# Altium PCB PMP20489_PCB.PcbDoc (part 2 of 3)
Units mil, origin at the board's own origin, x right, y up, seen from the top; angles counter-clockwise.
Board outline 4000 x 6000 mil, 8 copper layers (Top Layer, Signal Layer 1, Signal Layer 2, Signal Layer 3, Signal Layer 4, Signal Layer 5, Signal Layer 6, Bottom Layer), stack 63 mil thick; 331 components, 128 nets, 876 pads, 1027 vias.
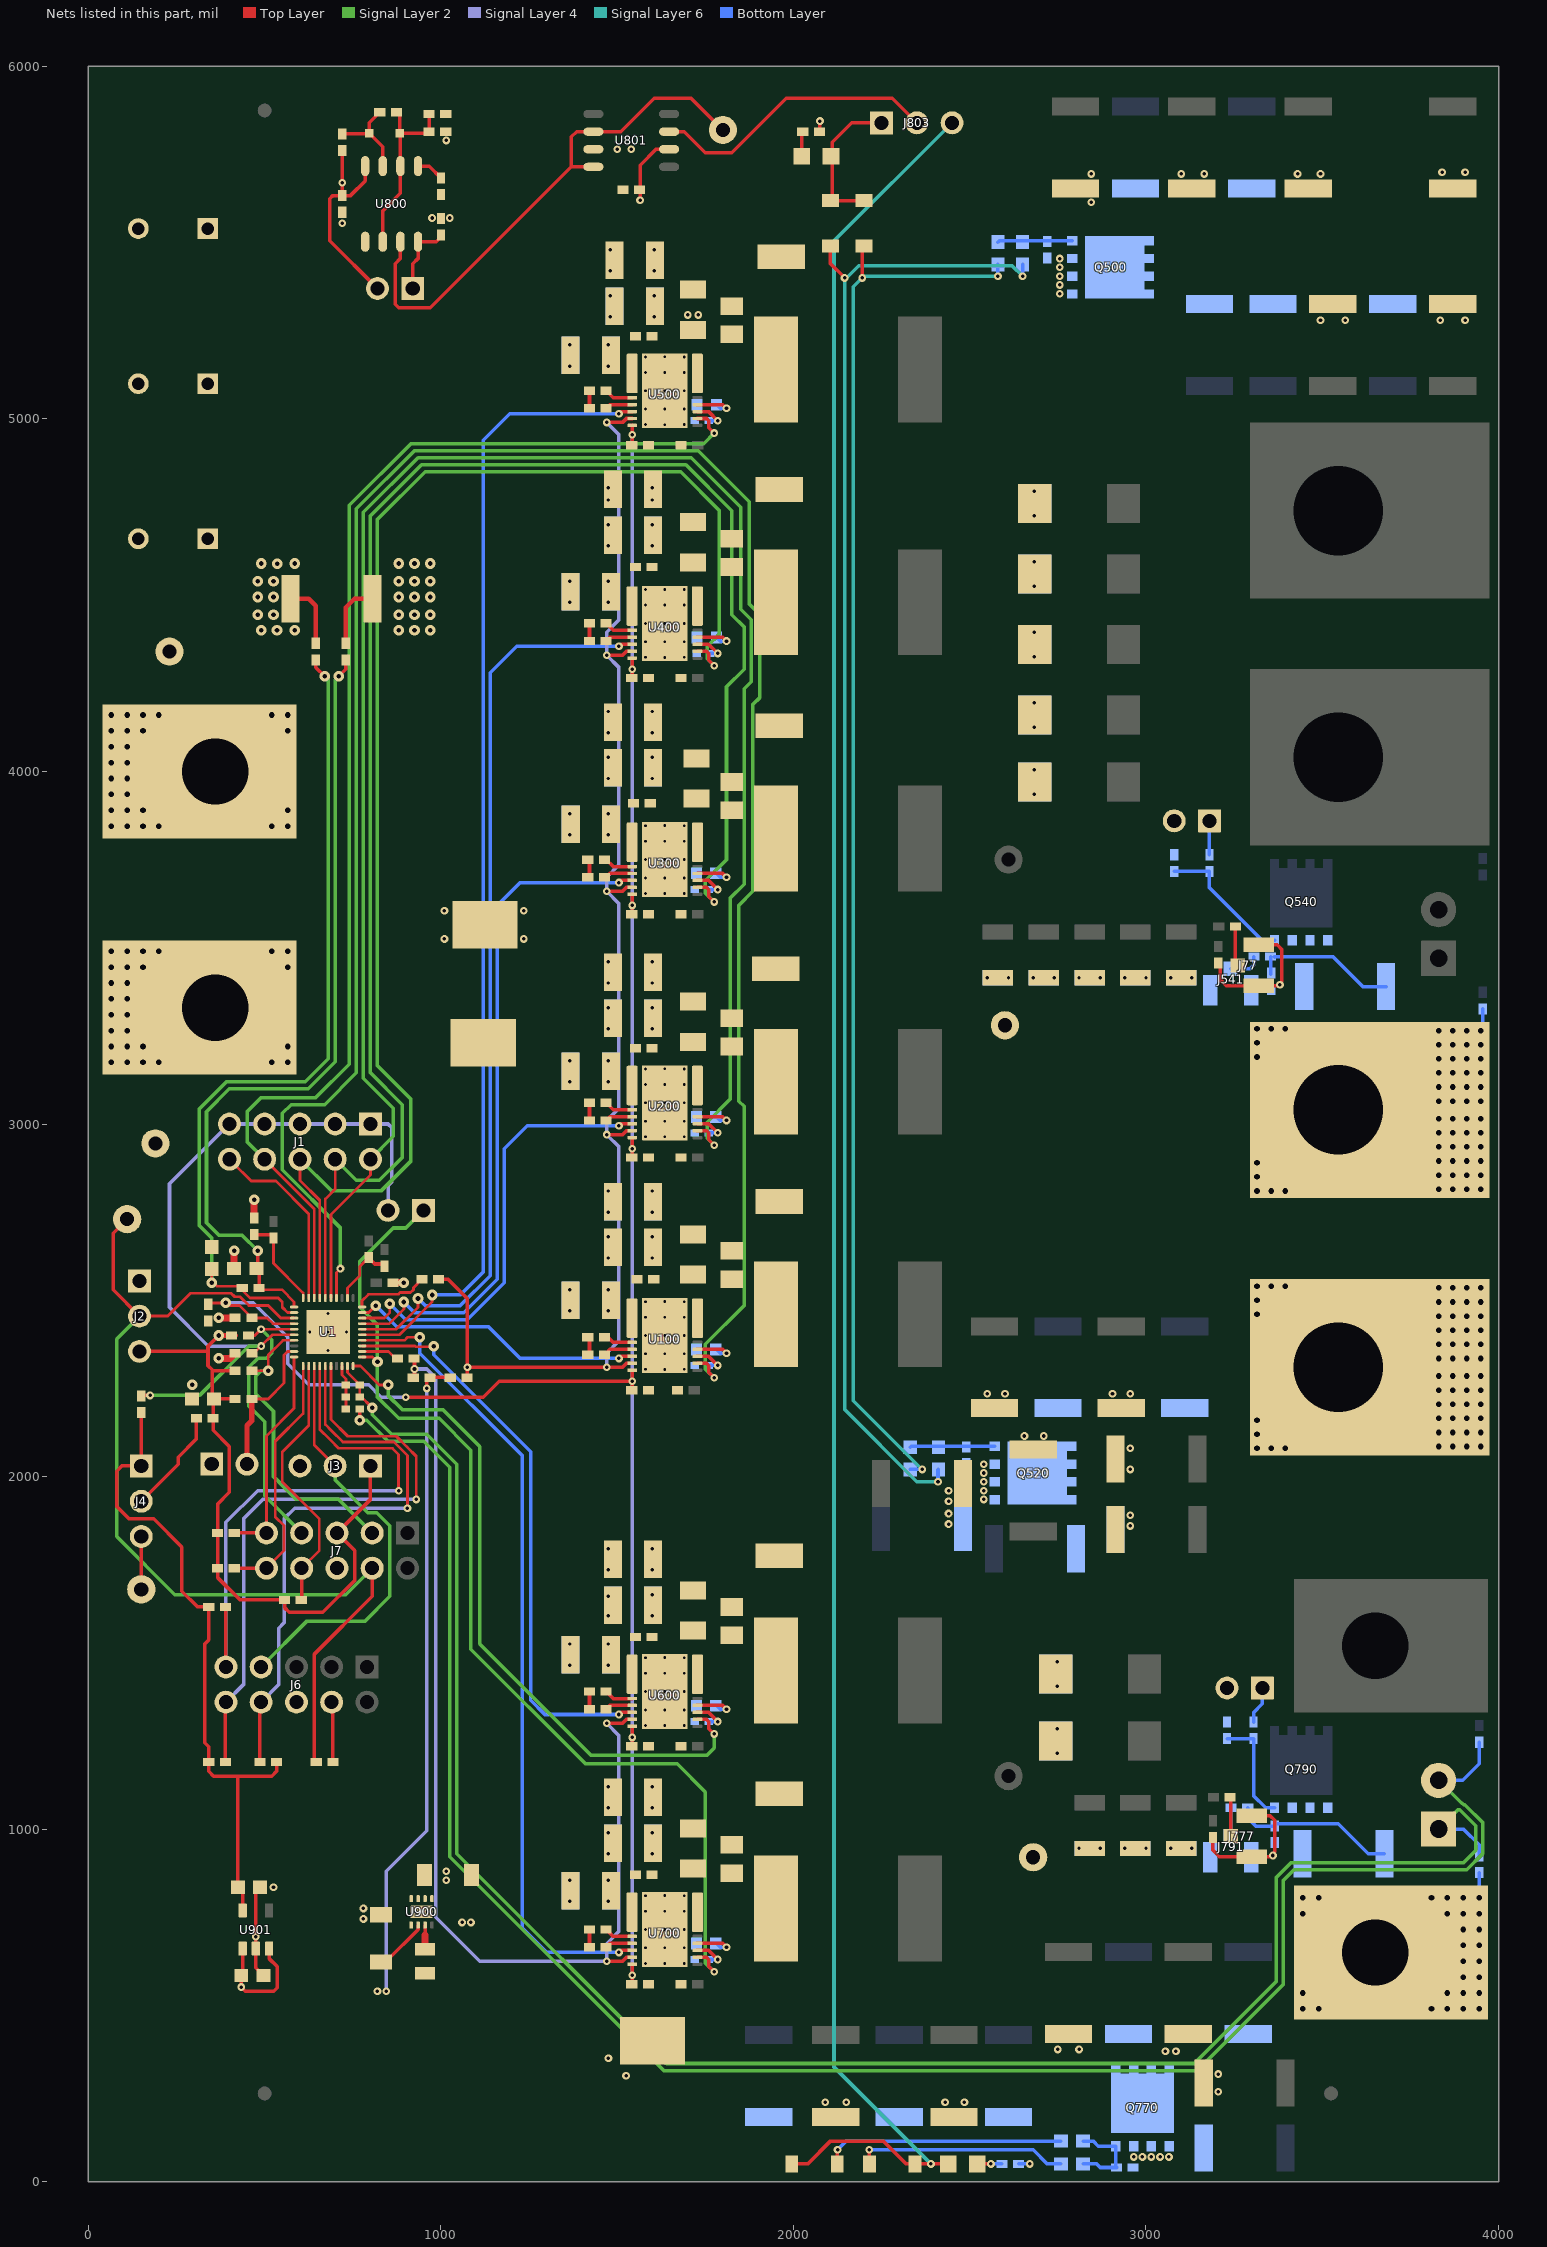
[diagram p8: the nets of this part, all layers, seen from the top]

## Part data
C1: "CAP, CERM, 4.7 µF, 10 V, +/- 20%, X5R, 0402"
C2 C7 C8 C902 C903: "CAP, CERM, 1 µF, 25 V, +/- 10%, X5R, 0603"
C3 C6: "CAP, CERM, 1 µF, 10 V, +/- 10%, X7S, 0402"
C4: "CAP, CERM, 2200 pF, 50 V, +/- 10%, X7R, 0402"
C5 C60: "CAP, CERM, 1000 pF, 50 V, +/- 10%, X7R, 0402"
C11 C12 C13: "CAP, AL, 470 µF, 35 V, +/- 20%, TH"
C21 C22 C23 C24 C25 C26 C27 C28 C29 C30 C721 C722 C723 C724: "CAP, Aluminum Polymer, 470 µF, 2.5 V, +/- 20%, 9 ohm, 7.3x1.8x4.3mm SMD"
C31 C32 C33 C34 C35 C36 C37 C38 C39 C40 C725 C726 C727 C728 C729 C730: "CAP, CERM, 100 µF, 6.3 V, +/- 20%, X5R, 1210"
C77 C110 C210 C310 C410 C510 C540 C610 C710 C777 C790: "CAP, CERM, 0.1 µF, 25 V, +/- 10%, X5R, 0402"
C100 C200 C300 C400 C500 C600 C700: "CAP, CERM, 1000 pF, 25 V, +/- 5%, C0G/NP0, 0402"
C101 C102 C103 C104 C105 C201 C202 C203 C204 C205 C301 C302 C303 C304 C305 C401 C402 C403 C404 C405 C501 C502 C503 C504 C505 C601 C602 C603 C604 C605 C701 C702 C703 C704 C705: "CAP, CERM, 22 µF, 16 V, +/- 20%, X5R, 1210"
C106 C206 C306 C406 C506 C606 C706: "CAP, CERM, 3300 pF, 50 V, +/- 10%, X7R, 0402"
C111 C211 C311 C411 C511 C611 C711: "CAP, CERM, 10 µF, 6.3 V, +/- 20%, X5R, 0603"
C112 C212 C312 C412 C512 C612 C712: "CAP, CERM, 0.1 µF, 16 V, +/- 10%, X5R, 0402"
C113 C213 C313 C413 C513 C613 C713: "CAP, CERM, 1500 pF, 100 V, +/- 10%, X7R, 0805"
C800 C801 C802 C803: "CAP, CERM, 0.1 µF, 50 V, +/- 20%, X7R, 0402"
C804: "CAP, CERM, 1 µF, 10 V, +/- 10%, X5R, 0402"
C900: "CAP, CERM, 10 µF, 25 V, +/- 10%, X5R, 1206"
C901: "CAP, CERM, 22 µF, 6.3 V, +/- 10%, X5R, 1206"
D500: "LED, Red, SMD"
D502 D503 D770 D771: "Diode, Schottky, 30 V, 0.5 A, SOD-123"
D772: "LED, Green, SMD"
D800: "Diode, Schottky, 30 V, 0.2 A, SOD-323"
Dyn_Clk TP1 TP2 VIN Vout VoutB: "Test Point, Miniature, Red, TH"
FID1 FID2 FID3 FID4 FID5 FID6: "Fiducial mark.  There is nothing to buy or mount."
H1 H2 H3 H4: "Bumpon, Hemisphere, 0.375 X 0.235, Black"
J1 J7: "Header, 100mil, 5x2, Tin, TH"
J2 J3 J4 J803: "Header, 100mil, 3x1, Gold, TH"
J5 J8 J540 J790 J800: "Header, 100mil, 2x1, Gold, TH"
J6: "Header (shrouded), 100mil, 5x2, Gold, TH"
J11 J12 J701 J702: "Terminal 50A Lug"
J14 J703: "Terminal Block, 3.5mm Pitch, 2x1, TH"
J15 J16 J17 J18: "Terminal 90A Lug"
J77 J541 J777 J791: "Connector, Ultra-Mini Coaxial, SMD"
L100 L200 L300 L400 L500 L600 L700: "Inductor, Shielded Drum Core, Metal Composite, 210 nH, 68 A, 0.2 ohm, SMD"
L900: "Inductor, Shielded, Ferrite, 2.2 µH, 1.26 A, 0.066 ohm, SMD"
LBL1: library part THT-14-423-10, "Thermal Transfer Printable Labels, 0.650\" W x 0.200\" H - 10,000 per roll"
Logo3: library part FCC_disclaimer, "FCC_disclaimer"
Q500 Q520 Q770: "MOSFET, N-CH, 25 V, 113 A, DualCool SON 5x6mm"
Q540 Q790: "MOSFET, N-CH, 25 V, 100 A, SON 5x6mm"
R1 R10 R16: "RES, 1.0, 5%, 0.063 W, 0402"
R2 R6 R9: "RES, 9.76 M, 1%, 0.063 W, 0402"
R3: "RES, 121 k, 1%, 0.063 W, 0402"
R4: "RES, 412 k, 1%, 0.063 W, 0402"
R5: "RES, 154 k, 1%, 0.063 W, 0402"
R7 R8 R14 R23 R24 R25: "RES, 4.75 k, 1%, 0.063 W, 0402"
R11 R62 R66 R67: "RES, 0, 5%, 0.063 W, 0402"
R20 R21 R22 R101 R201 R301 R401 R501 R516 R536 R541 R601 R701 R788 R791 R811: "RES, 10.0 k, 1%, 0.063 W, 0402"
R41 R42: "RES, 10, 5%, 0.063 W, 0402"
R43: "RES, 0.001, 1%, 1 W, 2512"
R71 R72 R77 R543 R771 R772 R787 R793: "RES, 49.9, 1%, 0.063 W, 0402"
R110 R210 R310 R410 R510 R610 R710: "RES, 2.2, 5%, 0.063 W, 0402"
R113 R213 R313 R413 R513 R613 R713: "RES, 1.0, 5%, 0.5 W, 1206"
R505 R506 R507 R508 R509 R511 R512 R514 R515 R525 R526 R527 R528 R529 R530 R531 R532 R533 R534 R535 R550 R553 R775 R776 R777 R778 R780 R781 R782 R783 R784 R785 R786: "RES, 0.3, 1%, 2 W, 2512"
R521 R551 R773: "RES, 75.0, 1%, 0.1 W, 0603"
R522 R552 R774: "RES, 249, 1%, 0.1 W, 0603"
R523 R770: "RES, 330, 5%, 0.063 W, 0402"
R540 R790: "RES, 1.00 k, 1%, 0.063 W, 0402"
R542 R792: "RES, 0.01, 1%, 1 W, 2512"
R800: "RES, 8.06 k, 1%, 0.063 W, 0402"
R812: "RES, 200 k, 1%, 0.063 W, 0402"
RTN1 RTN6 TP199: "Test Point, Compact, SMT"
SW1 SW2 SW3 SW4 SW5 SW6 SW-B: "Test Point, Miniature, SMT"
U1: "Dual-Channel (6+1 or 5+2 Phases) D-CAP+ Step-Down Multiphase Controller with Non-Volitile Memory and PMBus Interface for VR13 Server VCORE, RSB0040E"
U100 U200 U300 U400 U500 U600 U700: "Synchronous Buck NexFET Power Stage, DMC0012A"
U800: "LinCMOS Timer, D0008A"
U801: "DUAL 4-A PEAK HIGH SPEED LOW- SIDE POWER MOSFET DRIVERS, D0008A"
U900: "Buck Step Down Regulator with 3 to 17 V Input and 5 V Output, -40 to 85 degC, 8-Pin WSON (DSG), Green (RoHS & no Sb/Br)"
U901: "Cap-Free, NMOS, 250mA Low Dropout Regulator with Reverse Current Protection, DBV0005A"
Vin_rtn Vout_rtn VoutB_rtn: "Test Point, Miniature, Black, TH"
ZZ2 ZZ3 ZZ4: library part AssemblyNote

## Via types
v1: diameter 32, hole 16, Top Layer to Bottom Layer, 344 vias
v2: diameter 22, hole 10, Top Layer to Bottom Layer, tented both sides, 216 vias
v3: diameter 30, hole 13, Top Layer to Bottom Layer, tented both sides, 211 vias
v4: diameter 22, hole 9.7, Top Layer to Bottom Layer, 144 vias
v5: diameter 19.68, hole 7.87, Top Layer to Bottom Layer, 112 vias

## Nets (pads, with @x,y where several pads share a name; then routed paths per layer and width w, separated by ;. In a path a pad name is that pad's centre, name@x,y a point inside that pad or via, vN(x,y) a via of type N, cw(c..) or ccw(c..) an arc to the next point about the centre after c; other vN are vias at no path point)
3.3V: C903.2 J4.1 R1.1 R20.2 R21.2 R22.2 U901.5 | length 1873
  Top Layer w10: R1.1@150,2181.38 J4.1@150,2030 95,2030 80,2015 80,1915 115,1880 185,1880 265,1800 265,1675 310,1630 R20.2@341.38,1630 341.38,1536.38 330,1525 330,1245 341.38,1233.62 R21.2@341.38,1190 341.38,1163.62 355,1150 425,1150 ; U901.5@437.6,769.13 437.6,821.22 C903.2@423.82,835 423.82,1148.82 425,1150 ; R22.2@533.62,1190 533.62,1163.62 520,1150 425,1150
5V: C111.1 C211.1 C311.1 C411.1 C511.1 C611.1 C711.1 C800.1 C804.1 C901.1 C902.2 J800.2 L900.2 R66.1 R67.1 R800.2 U100.4 U200.4 U300.4 U400.4 U500.4 U600.4 U700.4 U800.8 U801.6 U900.6 U901.1 U901.3 | length 3999.5
  Top Layer w10: U901.1@437.6,660.87 437.6,589.09 C902.2@433.5,585 v2(433.5,551.81) 445.31,540 525.31,540 535.31,550 535.31,610 512.4,632.91 U901.3@512.4,660.87 ; R800.2@720,5761.38 v2(720,5670) C800.1@720,5633.62 ; U800.8@785,5717.28 785,5675 743.62,5633.62 C800.1@720,5633.62 ; J800.2@820,5370 685,5505 685,5625 693.62,5633.62 C800.1@720,5633.62 ; C901.1@830,628.07 848.07,628.07 935.16,715.16 U900.6@935.16,727.6 ; L900.2@955,591.54 L900.2@966.81,579.72 ; v2(960,2250) 960,2281.38 R67.1@1026.38,2281.38 ; v2(1565,5620) 1565,5720 1610,5765 U801.6@1647.28,5765 ; U700.4@1727.52,675.62 1799.38,675.62 v2(1810,665) ; U600.4@1727.52,1350.62 1799.38,1350.62 v2(1810,1340) ; U100.4@1727.52,2360.62 1799.38,2360.62 v2(1810,2350) ; U200.4@1727.52,3020.62 1799.38,3020.62 v2(1810,3010) ; U300.4@1727.52,3710.62 1799.38,3710.62 v2(1810,3700) ; U400.4@1727.52,4380.62 1799.38,4380.62 v2(1810,4370) ; U500.4@1727.52,5040.62 1799.38,5040.62 v2(1810,5030)
  Signal Layer 4 w10: v2(845,540) 845,880 960,995 v2(960,2250)
  Bottom Layer w10: C711.1@1782.56,675 1792.56,665 v2(1810,665) ; C611.1@1782.56,1350 1792.56,1340 v2(1810,1340) ; C111.1@1782.56,2360 1792.56,2350 v2(1810,2350) ; C211.1@1782.56,3020 1792.56,3010 v2(1810,3010) ; C311.1@1782.56,3710 1792.56,3700 v2(1810,3700) ; C411.1@1782.56,4380 1792.56,4370 v2(1810,4370) ; C511.1@1782.56,5040 1792.56,5030 v2(1810,5030)
  other v2: 820,540
A_PIN11: R2.2 R67.2 U100.11 U200.11 U300.11 U400.11 U500.11 | length 3901.4
  Top Layer w10: R2.2@993.62,2560 1020,2560 1075,2505 v2(1075,2310) 1075,2281.38 R67.2@1073.62,2280 ; v2@1080,2310 v2(1470,2310) 1515,2310 1526.24,2321.24 U100.11@1542.48,2321.24 ; v2(1470,2970) 1515,2970 1526.24,2981.24 U200.11@1542.48,2981.24 ; v2(1470,3660) 1515,3660 1526.24,3671.24 U300.11@1542.48,3671.24 ; v2(1470,4330) 1515,4330 1526.24,4341.24 U400.11@1542.48,4341.24 ; v2(1470,4990) 1515,4990 1526.24,5001.24 U500.11@1542.48,5001.24
  Signal Layer 4 w10: v2(1470,2310) 1470,2350 1505,2385 1505,2935 v2(1470,2970) 1470,3010 1505,3045 1505,3625 v2(1470,3660) 1470,3700 1505,3735 1505,4295 v2(1470,4330) 1470,4395 1505,4430 1505,4955 v2(1470,4990)
ALERT#: J6.8 R22.1 U1.25 | length 1670.8
  Top Layer w7.87: U1.25@672.13,2313.54 672.13,2147.87 690,2130 721.69,2098.31 866.68,2098.31
  Top Layer w8: 866.68,2098.31 905,2060 v2@905,1905
  Top Layer w10: R22.1@486.38,1190 486.38,1356.38 J6.8@490,1360
  Signal Layer 4 w10: J6.8@490,1360 540,1410 540,1570 555,1585 555,1880 585,1910 v2(905,1910)
AVR_RDY: J7.3 R7.1 U1.17 | length 875
  Top Layer w7.87: R7.1@463.62,2300 v3(510,2300) 510,2344.54 551.84,2386.38 U1.17@583.54,2386.38
  Signal Layer 2 w10: v3(510,2300) 490,2300 475,2285 475,2235 525,2185 525,2000 590,1935 710,1935 J7.3@805,1840
B_PIN11: R6.2 R66.2 U600.11 U700.11 | length 3052.5
  Top Layer w10: R66.2@921.38,2280 925,2283.62 v2(925,2305) 925,2333.62 R6.2@923.62,2335 ; v2(1470,625) 1515,625 1526.24,636.24 U700.11@1542.48,636.24 ; v2(1470,1300) 1515,1300 1526.24,1311.24 U600.11@1542.48,1311.24
  Signal Layer 4 w10: v2(925,2305) 960,2305 985,2280 985,750 1110,625 v2(1470,625) 1470,675 1505,710 1505,1265 v2(1470,1300)
BCSP1: U1.30 U600.2 | length 1951.2
  Top Layer w7.87: U1.30@750.87,2313.54 771.46,2313.54 825,2260 v3(850,2260)
  Top Layer w10: U600.2@1727.52,1311.24 1753.45,1311.24 1760,1304.69 1760,1285 v2(1775,1270)
  Signal Layer 2 w10: v3(850,2260) 850,2230 890,2190 1005,2190 1110,2085 1110,1525 1425,1210 1755,1210 1775,1230 v2(1775,1270)
BCSP2: J8.1 U1.31 U700.2 | length 3016.5
  Top Layer w7.87: U1.31@776.46,2339.13 805.87,2339.13 v3(820,2325)
  Top Layer w10: U700.2@1727.52,636.24 1753.45,636.24 1760,629.69 1760,610 v2(1775,595)
  Signal Layer 2 w10: J8.1@950,2755 900,2705 865,2705 770,2610 770,2480 820,2430 v3(820,2325) 820,2225 880,2165 995,2165 1085,2075 1085,1510 1410,1185 1670,1185 1750,1105 1750,620 v2(1775,595)
BEN_VCCIO: J2.2 J7.4 R16.2 TP1.1 U1.13 | length 2915.5
  Top Layer w7.87: J2.2@145,2455 225,2455 290,2520 405,2520 415,2510 430,2510 455,2485 510,2485 545.63,2449.37 U1.13@583.54,2449.37
  Top Layer w10: TP1.1@110,2730 70,2690 70,2530 J2.2@145,2455 ; R16.2@646.38,1190 645,1190 640,1195 640,1495 805,1660 J7.4@805,1740
  Signal Layer 2 w10: J2.2@145,2455 80,2390 80,1830 245,1665 730,1665 J7.4@805,1740
BIAS: C7.1 J2.3 J3.1 J7.5 R7.2 R8.2 R10.1 R14.1 R23.1 R24.2 R25.1 | length 1992.6
  Top Layer w10: J2.3@145,2355 339.21,2355 ; 351.5,2300 R7.2@416.38,2300 R7.2@411.38,2305 ; 351.5,2302.28 351.5,2225 C7.1@353.62,2222.87 ; 353.78,2300 339.21,2314.57 339.21,2355 ; v3(370,2400) 339.21,2369.21 339.21,2355 ; R14.1@416.38,2220 C7.1@356.5,2220 C7.1@353.62,2222.87 ; J3.1@825,2030 800,2005 800,1935 J7.5@705,1840 755,1790 755,1705 665,1615 570,1615 556.38,1628.62 R23.1@556.38,1650 430,1650 366.38,1713.62 R25.1@366.38,1740 R24.2@366.38,1840 366.38,1921.38 400,1955 400,2085 353.62,2131.38 C7.1@353.62,2222.87
  Top Layer w15: v3(370,2400) R8.2@416.38,2400
BPWM1: U1.33 U600.10 | length 1620.7
  Top Layer w7.87: U1.33@776.46,2370.63 926.45,2370.63 928.89,2368.19 968.19,2368.19 v3@970,2370
  Top Layer w10: v2(1505,1325) 1510.93,1330.93 U600.10@1542.48,1330.93
  Bottom Layer w10: v3(980,2370) 980,2345 1255,2070 1255,1365 1295,1325 v2(1505,1325)
BPWM2: U1.34 U700.10 | length 2306.2
  Top Layer w7.87: U1.34@776.46,2386.38 896.38,2386.38 905,2395 v3(940,2395)
  Top Layer w10: v2(1505,650) 1510.93,655.93 U700.10@1542.48,655.93
  Bottom Layer w10: v3(940,2395) 940,2350 1230,2060 1230,720 1300,650 v2(1505,650)
BVR_RDY: J7.7 R8.1 U1.15 | length 821.4
  Top Layer w7.87: R8.1@463.62,2400 471.99,2400 v2(489.86,2417.87) U1.15@583.54,2417.87
  Signal Layer 2 w10: v2(489.86,2417.87) 520,2387.74 520,2350 505,2335 480,2335 455,2310 455,2200 500,2155 500,1945 J7.7@605,1840
BVSN: C5.1 J703.1 R9.2 R772.1 U1.29 | length 5513.5
  Top Layer w7.87: U1.29@735.12,2313.54 735.12,2294.88 770,2260 770,2230 v3(805,2195)
  Signal Layer 2 w10: v3(805,2195) 805,2175 860,2120 960,2120 1045,2035 1045,930 1640,335 3136.72,335 3370,568.28 3370,863.28 3411.72,905 3901.72,905 3935.86,939.14 3935.86,1009.14 3890,1055 3885,1055 J703.1@3830,1000
  Bottom Layer w10: J703.1@3830,1000 3900,1000 3945,955 R772.1@3945,923.62
BVSP: J703.2 R11.2 R771.1 | length 5514.6
  Top Layer w10: R11.2@769.69,2191 770,2190.69 v3(770,2160)
  Signal Layer 2 w10: v3(770,2160) 790,2160 850,2100 951.72,2100 1025,2026.72 1025,921.72 1631.72,315 3145,315 3390,560 3390,855 3420,885 3910,885 3955.86,930.86 3955.86,1017.43 3904.14,1069.14 3901.03,1069.14 3897.37,1072.8 3895.2,1072.8 J703.2@3830,1138
  Bottom Layer w10: J703.2@3830,1138 3898,1138 3945,1185 R771.1@3945,1246.38
CHRG_1: D502.1 R521.1 R551.1 | length 4013.1
  Top Layer w10: v2(2195,5400) 2195,5480.53 D502.1@2205,5490.53
  Signal Layer 6 w10: v2@2360,2025 2170,2215 2170,5375 v2(2195,5400) 2200,5405 v2(2580,5405)
  Bottom Layer w10: R521.1@2331.3,2020.16 2331.46,2020 v2(2365,2020) ; v2(2580,5405) R551.1@2580,5438.5
CLK: J6.9 R20.1 U1.24 | length 1643.4
  Top Layer w7.87: U1.24@656.38,2313.54 656.38,2133.62 685,2105
  Top Layer w8: 685,2105 710,2080 862.55,2080 880,2062.55 v2(880,1960)
  Top Layer w10: R20.1@388.62,1630 390,1628.62 J6.9@390,1460
  Signal Layer 4 w10: J6.9@390,1460 390,1870 480,1960 v2(880,1960)
CSP1: U1.4 U100.2 | length 6358.1
  Top Layer w7.87: U1.4@703.62,2506.46 703.62,2578.62 v2(715,2590)
  Top Layer w10: U100.2@1727.52,2321.24 1753.45,2321.24 1760,2314.69 1760,2295 v2(1775,2280)
  Signal Layer 2 w10: v2(715,2590) 715,2705 550,2870 550,3030 575,3055 670,3055 760,3145 760,4745 925,4910 1730,4910 1875,4765 1875,4475 1905,4445 1905,4210 1885,4190 1885,3660 1845,3620 1845,3065 1860,3050 1860,2485 1750,2375 1750,2305 v2(1775,2280)
CSP2: J1.2 U1.5 U200.2 | length 5487.9
  Top Layer w7.87: U1.5@687.87,2506.46 687.87,2742.87 800,2855 J1.2@800,2900
  Top Layer w10: U200.2@1727.52,2981.24 1753.45,2981.24 1760,2974.69 1760,2955 v2(1775,2940)
  Signal Layer 2 w10: J1.2@800,2900 865,2965 865,3045 780,3130 780,4735 935,4890 1710,4890 1850,4750 1850,4460 1880,4430 1880,4255 1860,4235 1860,3680 1820,3640 1820,3070 1755,3005 1755,2960 v2(1775,2940)
CSP3: J1.4 U1.6 U300.2 | length 4899.6
  Top Layer w7.87: U1.6@672.13,2506.46 672.13,2787.13 700,2815 J1.4@700,2900
  Top Layer w10: U300.2@1727.52,3671.24 1753.45,3671.24 1760,3664.69 1760,3645 v2(1775,3630)
  Signal Layer 2 w10: J1.4@700,2900 760,2840 825,2840 890,2905 890,3055 800,3145 800,4725 945,4870 1695,4870 1825,4740 1825,4445 1860,4410 1860,4290 1810,4240 1810,3750 1750,3690 1750,3655 v2(1775,3630)
CSP4: J1.6 U1.7 U400.2 | length 4274.1
  Top Layer w7.87: J1.6@600,2900 600,2840 656.38,2783.62 U1.7@656.38,2506.46
  Top Layer w10: U400.2@1727.52,4341.24 1753.45,4341.24 1760,4334.69 1760,4315 v2(1775,4300)
  Signal Layer 2 w10: J1.6@600,2900 690,2810 830,2810 915,2895 915,3070 820,3165 820,4715 955,4850 1680,4850 1790,4740 1790,4390 1755,4355 1755,4320 v2(1775,4300)
CSP5: J1.8 U1.8 U500.2 | length 3734.4
  Top Layer w7.87: J1.8@500,2900 640.63,2759.37 U1.8@640.63,2506.46
  Top Layer w10: U500.2@1727.52,5001.24 1753.45,5001.24 1760,4994.69 1760,4975 v2(1775,4960)
  Signal Layer 2 w10: J1.8@500,2900 450,2950 450,3035 490,3075 645,3075 740,3170 740,4755 915,4930 1745,4930 v2(1775,4960)
CSP6: J1.10 U1.9 | length 527.1
  Top Layer w7.87: J1.10@407.5,2902.5 407.5,2892.5 461.85,2838.15 531.85,2838.15 624.88,2745.12 U1.9@624.88,2506.46
CSPIN: C3.2 C8.1 R42.2 U1.12 | length 2390.3
  Top Layer w7.87: C8.1@350,2588.5 350,2555 365,2540 425,2540 458.62,2506.38 538.62,2506.38 550,2495 550,2480.24 565.12,2465.12 U1.12@583.54,2465.12
  Top Layer w10: R42.2@645,4316.38 645,4295 v3(670,4270)
  Signal Layer 2 w10: v3(350,2550) 350,2676.72 315,2711.72 315,3043.28 391.72,3120 615,3120 680,3185 680,4260 v3(670,4270)
DATA: J6.10 R21.1 U1.26 | length 1783.5
  Top Layer w7.87: 687.87,2182.6 U1.26@687.87,2313.54
  Top Layer w8: 687.87,2182.6 687.87,2162.13 735.81,2114.19 873.36,2114.19 904.19,2083.36 904.19,2083.26 930,2057.45 v2(930,1935)
  Top Layer w10: R21.1@388.62,1190 388.62,1358.62 J6.10@390,1360
  Signal Layer 4 w10: J6.10@390,1360 440,1410 440,1880 495,1935 v2(930,1935)
DIS_1: D503.2 R522.1 R552.1 | length 4267.3
  Top Layer w10: D503.2@2110,5490.53 2105,5485.53 2105,5440 v2(2145,5400)
  Signal Layer 6 w10: v2(2410,1985) 2350,1985 2145,2190 2145,5395 2185,5435 2620,5435 v2(2650,5405)
  Bottom Layer w10: v2(2410,1985) 2410,2018.86 R522.1@2411.3,2020.16 ; v2(2650,5405) R552.1@2650,5438.5
DYN_2: D770.2 D771.1 D772.1 J803.3 | length 6539.6
  Top Layer w10: D770.2@1995.53,50 2040,50 2105,115 2255,115 2320,50 D771.1@2344.47,50 v2(2390,50) D772.1@2438.66,50
  Signal Layer 6 w10: v2(2390,50) 2115,325 2115,5505 J803.3@2450,5840
GND: C1.2 C2.2 C4.2 C6.2 C7.2 C8.2 C11.2 C12.2 C13.2 C21.2 C22.2 C23.2 C24.2 C25.2 C26.2 C27.2 C28.2 C29.2 C30.2 C31.2 C32.2 C33.2 C34.2 C35.2 C36.2 C37.2 C38.2 C39.2 C40.2 C77.2 C100.1 C101.2 C102.2 C103.2 C104.2 C105.2 C106.2 C111.2 C112.2 C200.1 C201.2 C202.2 C203.2 C204.2 C205.2 C206.2 C211.2 C212.2 C300.1 C301.2 C302.2 C303.2 C304.2 C305.2 C306.2 C311.2 C312.2 C400.1 C401.2 C402.2 C403.2 C404.2 C405.2 C406.2 C411.2 C412.2 C500.1 C501.2 C502.2 C503.2 C504.2 C505.2 C506.2 C511.2 C512.2 C540.2 C600.1 C601.2 C602.2 C603.2 C604.2 C605.2 C606.2 C611.2 C612.2 C700.1 C701.2 C702.2 C703.2 C704.2 C705.2 C706.2 C711.2 C712.2 C721.2 C722.2 C723.2 C724.2 C725.2 C726.2 C727.2 C728.2 C729.2 C730.2 C777.2 C790.2 C800.2 C801.2 C802.2 C803.2 C804.2 C900.2 C901.2 C902.1 C903.1 J2.1 J3.3 J5.1 J6.6 J7.6 J12.1 J17.1 J18.1 J77.2 J77.3 J540.2 J541.2 J541.3 J702.1 J777.2 J777.3 J790.2 J791.2 J791.3 Q500.1 Q500.2 Q500.3 Q520.1 Q520.2 Q520.3 Q770.1 Q770.2 Q770.3 R3.1 R5.1 R72.2 R101.1 R113.1 R201.1 R213.1 R301.1 R313.1 R401.1 R413.1 R501.1 R513.1 R516.1 R523.1 R536.1 R541.1 R542.1 R601.1 R613.1 R701.1 R713.1 R770.1 R772.2 R788.1 R791.1 R792.1 R811.1 RTN1.1 RTN6.1 U1.41 U100.13@1635,2400 U200.13@1635,3060 U300.13@1635,3750 U400.13@1635,4420 U500.13@1635,5080 U600.13@1635,1390 U700.13@1635,715 U800.1 U801.3 U900.1 U900.4 U900.5 U900.9 U901.2 Vin_rtn.1 Vout_rtn.1 VoutB_rtn.1 | length 1456.1
  Top Layer w10: C903.1@486.81,835 475,823.19 U901.2@475,660.87 475,606.5 C902.1@496.5,585 ; R523.1@2073.62,5815 2075,5816.38 v2(2075,5845) ; C777.2@3190,976.38 3190,940 3208.07,921.93 J777.3@3300,921.93 3351.93,921.93 3365,935 3365,1025 3351.93,1038.07 J777.2@3300,1038.07 ; C77.2@3210,3446.38 3210,3410 3228.07,3391.93 J77.3@3320,3391.93 3371.93,3391.93 3385,3405 3385,3495 3371.93,3508.07 J77.2@3320,3508.07
  Top Layer w20: v3(370,2335) 401.38,2335 C1.2@416.38,2350 ; v3(370,2450) C4.2@416.38,2450 ; C2.2@413.5,2590 v3@413.5,2636.5 ; R5.1@470,2733.62 v3(470,2785) ; C6.2@863.62,2550 v3(895,2550)
  Bottom Layer w10: R770.1@2638.62,50 v2(2670,50) ; v1(3945,805) R772.2@3945,876.38 ; J17.1@3955,3265 R72.2@3955,3326.38
  other v1: 3445,490 3490,490 3810,490 3855,490 3900,490 3945,490 3445,535 3855,535 3900,535 3945,535 3900,580 3945,580 3900,625 3945,625 3900,670 3945,670 3900,715 3945,715 3445,760 3855,760 3900,760 3945,760 3445,805 3490,805 3810,805 3855,805 3900,805 3315,2080 3355,2080 3395,2080 3830,2085 3870,2085 3910,2085 3950,2085 3315,2120 3830,2125 3870,2125 3910,2125 3950,2125 3315,2160 3830,2165 3870,2165 3910,2165 3950,2165 3830,2205 3870,2205 3910,2205 3950,2205 3830,2245 3870,2245 3910,2245 3950,2245 3830,2285 3870,2285 3910,2285 3950,2285 3830,2335 3870,2335 3910,2335 3950,2335 3830,2375 3870,2375 3910,2375 3950,2375 3830,2415 3870,2415 3910,2415 3950,2415 3830,2455 3870,2455 3910,2455 3950,2455 3315,2460 3830,2495 3870,2495 3910,2495 3950,2495 3315,2500 3830,2535 3870,2535 3910,2535 3950,2535 3315,2540 3355,2540 3395,2540 3315,2810 3355,2810 3395,2810 3830,2815 3870,2815 3910,2815 3950,2815 3315,2850 3830,2855 3870,2855 3910,2855 3950,2855 3315,2890 3830,2895 3870,2895 3910,2895 3950,2895 3830,2935 3870,2935 3910,2935 3950,2935 3830,2975 3870,2975 3910,2975 3950,2975 3830,3015 3870,3015 3910,3015 3950,3015 3830,3065 3870,3065 3910,3065 3950,3065 3830,3105 3870,3105 3910,3105 3950,3105 3830,3145 3870,3145 3910,3145 3950,3145 65,3175 110,3175 155,3175 200,3175 520,3175 565,3175 3830,3185 3870,3185 3910,3185 3950,3185 3315,3190 65,3220 110,3220 155,3220 565,3220 3830,3225 3870,3225 3910,3225 3950,3225 3315,3230 65,3265 110,3265 3830,3265 3870,3265 3910,3265 3950,3265 3315,3270 3355,3270 3395,3270 65,3310 110,3310 65,3355 110,3355 65,3400 110,3400 65,3445 110,3445 155,3445 565,3445 65,3490 110,3490 155,3490 200,3490 520,3490 565,3490
  other v2: 2965,70 2990,70 3015,70 3040,70 3065,70 1525,300 1475,350 475,695 1060,735 1085,735 780,745 780,775 525,835 3360,925 2540,1935 2540,1960 2540,1985 2540,2010 2540,2035 3380,3395 1700,5295 1730,5295 2755,5355 2755,5380 2755,5405 2755,5430 2755,5455 720,5555 975,5570 1025,5570 1500,5765 1540,5765 1015,5790
  other v3: 295,2260 413.5,2640
  other v4: 1365,795 1365,855 1600,930 2810,945 2870,945 2940,945 3000,945 3070,945 3130,945 1600,990 1600,1060 1600,1120 2748.03,1215 2748.03,1285 2748.03,1405 1365,1465 2748.03,1475 1365,1525 1600,1605 1600,1665 1600,1735 1600,1795 1365,2470 1365,2530 1600,2620 1600,2680 1600,2750 1600,2810 1365,3120 1365,3180 1600,3270 1600,3330 1600,3400 2550,3415.08 2610,3415.08 2680,3415.08 2740,3415.08 2810,3415.08 2870,3415.08 2940,3415.08 3000,3415.08 3070,3415.08 3130,3415.08 1600,3460 1365,3820 1365,3880 2683.03,3935 1600,3980 2683.03,4005 1600,4040 1600,4110 2683.03,4125 1600,4170 2683.03,4195 2683.03,4325 2683.03,4395 1365,4480 2683.03,4525 1365,4540 2683.03,4595 1600,4640 1600,4700 2683.03,4725 1600,4770 2683.03,4795 1600,4805 1365,5150 1365,5210 1605,5290 1605,5350 1605,5420 1605,5480
  other v5: 1580,619 1635,618.54 1690,619 1579.88,663.03 1635,663.03 1690.12,663.03 1579.88,715 1635,715 1690.12,715 929.25,765 960.75,765 1579.88,766.97 1635,766.97 1690.12,766.97 1580,811 1635,811.46 1690,811 1580,1294 1635,1293.54 1690,1294 1579.88,1338.03 1635,1338.03 1690.12,1338.03 1579.88,1390 1635,1390 1690.12,1390 1579.88,1441.97 1635,1441.97 1690.12,1441.97 1580,1486 1635,1486.46 1690,1486 1580,2304 1635,2303.54 1690,2304 1579.88,2348.03 1635,2348.03 1690.12,2348.03 680,2357.83 1579.88,2400 1635,2400 1690.12,2400 627.83,2410 680,2410 732.17,2410 1579.88,2451.97 1635,2451.97 1690.12,2451.97 680,2462.17 1580,2496 1635,2496.46 1690,2496 1580,2964 1635,2963.54 1690,2964 1579.88,3008.03 1635,3008.03 1690.12,3008.03 1579.88,3060 1635,3060 1690.12,3060 1579.88,3111.97 1635,3111.97 1690.12,3111.97 1580,3156 1635,3156.46 1690,3156 1580,3654 1635,3653.54 1690,3654 1579.88,3698.03 1635,3698.03 1690.12,3698.03 1579.88,3750 1635,3750 1690.12,3750 1579.88,3801.97 1635,3801.97 1690.12,3801.97 1580,3846 1635,3846.46 1690,3846 1580,4324 1635,4323.54 1690,4324 1579.88,4368.03 1635,4368.03 1690.12,4368.03 1579.88,4420 1635,4420 1690.12,4420 1579.88,4471.97 1635,4471.97 1690.12,4471.97 1580,4516 1635,4516.46 1690,4516 1580,4984 1635,4983.54 1690,4984 1579.88,5028.03 1635,5028.03 1690.12,5028.03 1579.88,5080 1635,5080 1690.12,5080 1579.88,5131.97 1635,5131.97 1690.12,5131.97 1580,5176 1635,5176.46 1690,5176
MAIN_ENABLE: J3.2 J6.7 U1.23 | length 1226.9
  Top Layer w7.87: 640.63,2270.63 U1.23@640.63,2313.54
  Top Layer w8: 640.63,2270.63 640.63,2089.37 J3.2@700,2030 J3.2@725,2030
  Signal Layer 2 w10: J6.7@490,1460 620,1590 785,1590 855,1660 855,1860 817.5,1897.5 792.5,1897.5 700,1990 700,2005 705,2010 J3.2@705,2025
NetC5_2: C5.2 R9.1 R11.1 U1.28 | length 127.1
  Top Layer w8: U1.28@719.37,2313.54 719.37,2287.63 730.31,2276.69 R11.1@730.32,2191
NetC60_1: C60.1 R62.1 U1.2 | length 192.4
  Top Layer w7.87: U1.2@735.12,2506.46 735.12,2535.12 770,2570 770,2596.38 C60.1@794.31,2620.69
  Top Layer w10: C60.1@794.31,2620.69 812.13,2602.87 838.5,2602.87 R62.1@840,2601.38
NetC110_1: C110.1 U100.8 | length 82
  Top Layer w10: C110.1@1468.62,2400 1488.31,2380.31 U100.8@1542.48,2380.31
NetC110_2: C110.2 R110.1 | length 50
  Top Layer w10: R110.1@1421.38,2350 C110.2@1421.38,2400
NetC113_1: C113.1 L100.1 SW1.1 U100.6
NetC113_2: C113.2 R113.2
NetC210_1: C210.1 U200.8 | length 82
  Top Layer w10: C210.1@1468.62,3060 1488.31,3040.31 U200.8@1542.48,3040.31
NetC210_2: C210.2 R210.1 | length 50
  Top Layer w10: R210.1@1421.38,3010 C210.2@1421.38,3060
NetC213_1: C213.1 L200.1 SW2.1 U200.6
NetC213_2: C213.2 R213.2
NetC310_1: C310.1 U300.8 | length 82
  Top Layer w10: C310.1@1468.62,3750 1488.31,3730.31 U300.8@1542.48,3730.31
NetC310_2: C310.2 R310.1 | length 50
  Top Layer w10: R310.1@1421.38,3700 C310.2@1421.38,3750
NetC313_1: C313.1 L300.1 SW3.1 U300.6
NetC313_2: C313.2 R313.2
NetC410_1: C410.1 U400.8 | length 82
  Top Layer w10: C410.1@1468.62,4420 1488.31,4400.31 U400.8@1542.48,4400.31
NetC410_2: C410.2 R410.1 | length 50
  Top Layer w10: R410.1@1421.38,4370 C410.2@1421.38,4420
NetC413_1: C413.1 L400.1 SW4.1 U400.6
NetC413_2: C413.2 R413.2
NetC510_1: C510.1 U500.8 | length 82
  Top Layer w10: C510.1@1468.62,5080 1488.31,5060.31 U500.8@1542.48,5060.31
NetC510_2: C510.2 R510.1 | length 50
  Top Layer w10: R510.1@1421.38,5030 C510.2@1421.38,5080
NetC513_1: C513.1 L500.1 SW5.1 U500.6
NetC513_2: C513.2 R513.2
NetC540_1: C540.1 Q540.1 Q540.2 Q540.3 R542.2 R543.1 | length 404.7
  Bottom Layer w10: C540.1@3353.62,3425 R543.1@3353.62,3475 ; R543.1@3365,3473.62 3363.62,3475 3530,3475 3615,3390 R542.2@3681.14,3390
NetC610_1: C610.1 U600.8 | length 82
  Top Layer w10: C610.1@1468.62,1390 1488.31,1370.31 U600.8@1542.48,1370.31
NetC610_2: C610.2 R610.1 | length 50
  Top Layer w10: R610.1@1421.38,1340 C610.2@1421.38,1390
NetC613_1: C613.1 L600.1 SW6.1 U600.6
NetC613_2: C613.2 R613.2
NetC710_1: C710.1 U700.8 | length 82
  Top Layer w10: C710.1@1468.62,715 1488.31,695.31 U700.8@1542.48,695.31
NetC710_2: C710.2 R710.1 | length 50
  Top Layer w10: R710.1@1421.38,665 C710.2@1421.38,715
NetC713_1: C713.1 L700.1 SW-B.1 U700.6
NetC713_2: C713.2 R713.2
NetC790_1: C790.1 Q790.1 Q790.2 Q790.3 R792.2 R793.1 | length 464.2
  Bottom Layer w10: R793.1@3288.62,1060 3288.62,1031.38 3311.38,1008.62 C790.1@3365,1008.62 3365,1010 3370,1015 3545,1015 3630,930 R792.2@3676.14,930
NetC801_1: C801.1 C802.1 D800.1 R812.1 U800.2 U800.6 | length 527.8
  Top Layer w10: U800.2@835,5502.72 835,5590 885,5640 U800.6@885,5717.28 885,5808.31 D800.1@883.31,5810 ; R812.1@873.62,5870 883.31,5860.31 D800.1@883.31,5810 ; C801.1@966.38,5865 C802.1@966.38,5815 961.38,5810 D800.1@883.31,5810
NetC803_1: C803.1 U800.5 | length 78.9
  Top Layer w10: U800.5@935,5717.28 966.34,5717.28 C803.1@1000,5683.62
NetD500_1: D500.1 D502.2 D503.1 J803.1 | length 423.3
  Top Layer w10: D502.2@2205,5619.47 2110,5619.47 2110,5785 2165,5840 J803.1@2250,5840
NetD500_2: D500.2 R523.2 | length 71.1
  Top Layer w10: D500.2@2023.66,5745 2023.66,5812.28 R523.2@2026.38,5815
NetD770_1: D770.1 R773.1 | length 684.1
  Top Layer w10: D770.1@2124.47,50 2124.47,89.47 v2(2125,90)
  Bottom Layer w10: v2(2125,90) 2150,115 R773.1@2758.5,115
NetD771_2: D771.2 R774.1 | length 600.3
  Top Layer w10: v2(2215,90) 2215.53,89.47 D771.2@2215.53,50
  Bottom Layer w10: v2(2215,90) 2680,90 2720,50 R774.1@2758.5,50
NetD772_2: D772.2 R770.2 | length 70
  Top Layer w10: D772.2@2521.34,50 v2(2560,50)
  Bottom Layer w10: v2(2560,50) R770.2@2591.38,50
NetD800_2: D800.2 R800.1 R812.2 U800.7 | length 258.1
  Top Layer w10: R800.1@720,5808.62 795.31,5808.62 D800.2@796.69,5810 ; R812.2@826.38,5870 796.69,5840.31 D800.2@796.69,5810 ; U800.7@835,5717.28 835,5771.69 D800.2@796.69,5810
NetDyn_Clk_1: Dyn_Clk.1 U800.3 U801.2 U801.4 | length 1514.2
  Top Layer w10: U800.3@885,5502.72 885,5455 870,5440 870,5325 880,5315 970,5315 1370,5715 ; U801.4@1432.72,5715 1370,5715 ; Dyn_Clk.1@1799.77,5819.65 1709.42,5910 1605,5910 1510,5815 U801.2@1432.72,5815 1385,5815 1370,5800 1370,5715
NetJ4_2: J4.2 R10.2 | length 299.8
  Top Layer w10: J4.2@150,1930 255,2035 255,2055 306.38,2106.38 R10.2@306.38,2165
NetJ4_3: J4.3 TP2.1 | length 150
  Top Layer w10: TP2.1@150,1680 J4.3@150,1830
NetJ6_4: J6.4 R16.1 | length 171.5
  Top Layer w10: J6.4@690,1360 693.62,1356.38 R16.1@693.62,1190
NetJ77_1: J77.1 R77.1 | length 112.6
  Top Layer w10: R77.1@3253.62,3560 3253.62,3456.34 J77.1@3259.96,3450
NetJ540_1: J540.1 R540.1 | length 96.4
  Bottom Layer w10: R540.1@3180,3763.62 J540.1@3180,3860
NetJ541_1: J541.1 R543.2 | length 94.1
  Bottom Layer w10: J541.1@3240,3440.04 3295.04,3440.04 3305,3450 R543.2@3305,3475
NetJ777_1: J777.1 R787.1 | length 111.5
  Top Layer w10: J777.1@3239.96,980 3239.96,1086.34 R787.1@3243.62,1090
NetJ790_1: J790.1 R790.1 | length 106.7
  Bottom Layer w10: R790.1@3305,1303.62 3305,1330 3330,1355 J790.1@3330,1400
NetJ791_1: J791.1 R793.2 | length 80.5
  Bottom Layer w10: J791.1@3240,980.04 3240,1058.62 R793.2@3241.38,1060
NetJ800_1: J800.1 R811.2 U800.4 | length 209.6
  Top Layer w10: J800.1@920,5370 920,5440 935,5455 U800.4@935,5502.72 986.34,5502.72 R811.2@1000,5516.38
NetJ803_2: J803.2 U801.7 | length 820.8
  Top Layer w10: U801.7@1647.28,5815 1690,5815 1750,5755 1825,5755 1980,5910 2280,5910 J803.2@2350,5840
NetL900_1: L900.1 U900.7 | length 69.2
  Top Layer w10: 954.84,700 U900.7@954.84,727.6
  Top Layer w20: 954.84,700 955,699.84 L900.1@955,658.46
NetQ500_4: Q500.4 R516.2 R551.2 R552.2 | length 212.4
  Bottom Layer w10: R551.2@2580,5501.5 2584,5505.49 Q500.4@2790.7,5505.49
NetQ500_5: Q500.5 Q500.6 Q500.7 Q500.8 Q500.10 R505.1 R506.1 R507.1 R508.1 R509.1 R511.1 R512.1 R514.1 R515.1 R550.1 R553.1
  other v2: 3495,5280 3565,5280 3835,5280 3905,5280 2845,5615 2845,5695 3100,5695 3165,5695 3430,5695 3495,5695 3840,5700 3905,5700
NetQ520_4: Q520.4 R521.2 R522.2 R536.2 | length 240.4
  Bottom Layer w10: R521.2@2331.3,2083.15 2333.64,2085.49 Q520.4@2570.7,2085.49
NetQ520_5: Q520.5 Q520.6 Q520.7 Q520.8 Q520.10 R525.1 R526.1 R527.1 R528.1 R529.1 R530.1 R531.1 R532.1 R533.1 R534.1 R535.1
  other v2: 2955,1860 2440,1865 2955,1890 2440,1895 2440,1930 2440,1960 2955,2020 2955,2080 2655,2115 2710,2115 2550,2235 2600,2235 2905,2235 2955,2235
NetQ540_4: Q540.4 R540.2 R541.2 | length 392.7
  Bottom Layer w10: R541.2@3080,3716.38 R540.2@3180,3716.38 3180,3670 3329.3,3520.7 Q540.4@3364.51,3520.7
NetQ770_4: Q770.4 R773.2 R774.2 R788.2 | length 259.4
  Bottom Layer w10: R774.2@2821.5,50 2860,50 2870,40 R788.2@2916.38,40 2914.51,41.87 Q770.4@2914.51,100.7 2864.3,100.7 2850,115 R773.2@2821.5,115
NetQ770_5: Q770.5 Q770.6 Q770.7 Q770.8 Q770.10 R775.1 R776.1 R777.1 R778.1 R780.1 R781.1 R782.1 R783.1 R784.1 R785.1 R786.1
  other v2: 2090,225 2150,225 2430,225 2485,225 3205,255 3205,305 3055,370 3085,370 2750,375 2810,375
NetQ790_4: Q790.4 R790.2 R791.2 | length 310.1
  Bottom Layer w10: R791.2@3230,1256.38 R790.2@3305,1256.38 3305,1095 3339.3,1060.7 Q790.4@3364.51,1060.7
NetR2_1: R2.1 U1.40 | length 216.5
  Top Layer w7.87: U1.40@776.46,2480.87 776.46,2498.69 794.58,2516.81 878.89,2516.81 883.89,2521.81 913.89,2521.81 922,2529.92 922,2535.62 R2.1@946.38,2560
NetR4_1: R4.1 R5.2 U1.10 | length 263.9
  Top Layer w7.87: R4.1@525,2676.38 525,2605 609.13,2520.87 U1.10@609.13,2506.46
  Top Layer w10: R5.2@470,2686.38 515,2686.38 R4.1@525,2676.38
NetR6_1: R6.1 U1.32 | length 103.2
  Top Layer w7.87: U1.32@776.46,2354.88 851.5,2354.88 R6.1@871.38,2335
NetR101_2: R101.2 U100.3 | length 93.5
  Top Layer w10: U100.3@1727.52,2340.93 1759.07,2340.93 v2(1785,2315)
  Bottom Layer w10: R101.2@1759.69,2315 v2(1785,2315)
NetR110_2: R110.2 U100.9 | length 78.3
  Top Layer w10: R110.2@1468.62,2350 1479.24,2360.62 U100.9@1542.48,2360.62
NetR201_2: R201.2 U200.3 | length 93.5
  Top Layer w10: U200.3@1727.52,3000.93 1759.07,3000.93 v2(1785,2975)
  Bottom Layer w10: R201.2@1759.69,2975 v2(1785,2975)
NetR210_2: R210.2 U200.9 | length 78.3
  Top Layer w10: R210.2@1468.62,3010 1479.24,3020.62 U200.9@1542.48,3020.62
NetR301_2: R301.2 U300.3 | length 93.5
  Top Layer w10: U300.3@1727.52,3690.93 1759.07,3690.93 v2(1785,3665)
  Bottom Layer w10: R301.2@1759.69,3665 v2(1785,3665)
NetR310_2: R310.2 U300.9 | length 78.3
  Top Layer w10: R310.2@1468.62,3700 1479.24,3710.62 U300.9@1542.48,3710.62
NetR401_2: R401.2 U400.3 | length 93.5
  Top Layer w10: U400.3@1727.52,4360.93 1759.07,4360.93 v2(1785,4335)
  Bottom Layer w10: R401.2@1759.69,4335 v2(1785,4335)
NetR410_2: R410.2 U400.9 | length 78.3
  Top Layer w10: R410.2@1468.62,4370 1479.24,4380.62 U400.9@1542.48,4380.62
NetR501_2: R501.2 U500.3 | length 93.5
  Top Layer w10: U500.3@1727.52,5020.93 1759.07,5020.93 v2(1785,4995)
  Bottom Layer w10: R501.2@1759.69,4995 v2(1785,4995)
NetR510_2: R510.2 U500.9 | length 78.3
  Top Layer w10: R510.2@1468.62,5030 1479.24,5040.62 U500.9@1542.48,5040.62
NetR601_2: R601.2 U600.3 | length 93.5
  Top Layer w10: U600.3@1727.52,1330.93 1759.07,1330.93 v2(1785,1305)
  Bottom Layer w10: R601.2@1759.69,1305 v2(1785,1305)
NetR610_2: R610.2 U600.9 | length 78.3
  Top Layer w10: R610.2@1468.62,1340 1479.24,1350.62 U600.9@1542.48,1350.62
NetR701_2: R701.2 U700.3 | length 93.5
  Top Layer w10: U700.3@1727.52,655.93 1759.07,655.93 v2(1785,630)
  Bottom Layer w10: R701.2@1759.69,630 v2(1785,630)
NetR710_2: R710.2 U700.9 | length 78.3
  Top Layer w10: R710.2@1468.62,665 1479.24,675.62 U700.9@1542.48,675.62
PWM1: U1.39 U100.10 | length 838.8
  Top Layer w7.87: U1.39@776.46,2465.12 795.12,2465.12 v3(815,2485)
  Top Layer w10: v2(1505,2335) 1510.93,2340.93 U100.10@1542.48,2340.93
  Bottom Layer w10: v3(815,2485) 875,2425 1135,2425 1225,2335 v2(1505,2335)
PWM2: U1.38 U200.10 | length 1269
  Top Layer w7.87: U1.38@776.46,2449.37 839.37,2449.37 855,2465 v3(855,2490)
  Top Layer w10: v2(1505,2995) 1510.93,3000.93 U200.10@1542.48,3000.93
  Bottom Layer w10: v3(855,2490) 900,2445 1075,2445 1180,2550 1180,2930 1245,2995 v2(1505,2995)
PWM3: U1.37 U300.10 | length 1944.3
  Top Layer w7.87: U1.37@776.46,2433.62 853.62,2433.62 895,2475 v3(895,2495)
  Top Layer w10: v2(1505,3685) 1510.93,3690.93 U300.10@1542.48,3690.93
  Bottom Layer w10: v3(895,2495) 925,2465 1065,2465 1160,2560 1160,3620 1225,3685 v2(1505,3685)
PWM4: U1.36 U400.10 | length 2603.8
  Top Layer w7.87: U1.36@776.46,2417.87 872.87,2417.87 935,2480 v3(935,2505)
  Top Layer w10: v2(1505,4355) 1510.93,4360.93 U400.10@1542.48,4360.93
  Bottom Layer w10: v3(935,2505) 955,2485 1055,2485 1140,2570 1140,4280 1215,4355 v2(1505,4355)
PWM5: U1.35 U500.10 | length 3242.7
  Top Layer w7.87: U1.35@776.46,2402.13 882.13,2402.13 975,2495 v3(975,2515)
  Top Layer w10: v2(1505,5015) 1510.93,5020.93 U500.10@1542.48,5020.93
  Bottom Layer w10: v3@977.27,2515 1055,2515 1120,2580 1120,4940 1195,5015 v2(1505,5015)
PWR_FLAGORRESET: J5.2 R14.2 U1.19 | length 413.3
  Top Layer w7.87: R14.2@463.62,2220 510,2220 555,2265 555,2345 564.88,2354.88 U1.19@583.54,2354.88
  Top Layer w15: J5.2@450,2035 450,2145 463.62,2158.62 R14.2@463.62,2220
SALERT#: J7.8 R23.2 U1.22 | length 759.3
  Top Layer w7.87: J7.8@605,1740 655,1790 655,1880 550,1985 550,2070 624.88,2144.88 U1.22@624.88,2313.54
  Top Layer w10: R23.2@603.62,1650 605,1651.38 J7.8@605,1740
SCLK: J7.9 R24.1 U1.20 | length 629.3
  Top Layer w7.87: J7.9@520,1840 505,1855 505,2115 583.54,2193.54 U1.20@583.54,2339.13
  Top Layer w10: R24.1@413.62,1840 J7.9@505,1840
SDIO: J7.10 R25.2 U1.21 | length 728.8
  Top Layer w7.87: J7.10@505,1740 555,1790 555,1860.57 530,1885.57 530,2100 609.13,2179.13 U1.21@609.13,2313.54
  Top Layer w10: R25.2@413.62,1740 J7.10@505,1740
TSEN: C4.1 C100.2 C200.2 C300.2 C400.2 C500.2 C600.2 C700.2 R3.2 U1.14 U100.12 U200.12 U300.12 U400.12 U500.12 U600.12 U700.12 | length 6362.8
  Top Layer w7.87: R3.2@340,2492.5 v3(390,2492.5) 392.5,2492.5 400,2485 428.62,2485 C4.1@463.62,2450 507.08,2450 523.46,2433.62 U1.14@583.54,2433.62
  Top Layer w10: v2(900,2225) 1120,2225 1165,2270 v2(1542.48,2270) ; C700.2@1541.38,560 1542.48,561.1 v2(1542.48,585) U700.12@1542.48,616.55 ; C600.2@1541.38,1235 1542.48,1236.1 v2(1542.48,1260) U600.12@1542.48,1291.55 ; C100.2@1541.38,2245 1542.48,2246.1 v2(1542.48,2270) ; C200.2@1541.38,2905 1542.48,2906.1 v2(1542.48,2930) U200.12@1542.48,2961.55 ; C300.2@1541.38,3595 1542.48,3596.1 v2(1542.48,3620) U300.12@1542.48,3651.55 ; C400.2@1541.38,4265 1542.48,4266.1 v2(1542.48,4290) U400.12@1542.48,4321.55 ; C500.2@1541.38,4925 1542.48,4926.1 U500.12@1542.48,4981.55 ; U100.12@1542.48,2301.55 v2(1542.48,2270)
  Signal Layer 4 w10: v3(390,2492.5) 467.5,2492.5 565,2395 565,2320 625,2260 795,2260 830,2225 v2(900,2225) ; v2(1542.48,585) v2(1542.48,1260) v2(1542.48,2270) v2(1542.48,2930) v2(1542.48,3620) v2(1542.48,4290) v2(1542.48,4955)
V3P3: C1.1 J1.1 J1.3 J1.5 J1.7 J1.9 J8.2 R1.2 U1.16 | length 2139.3
  Top Layer w7.87: C1.1@463.62,2350 470,2350 v2(490,2370) 522.13,2402.13 U1.16@583.54,2402.13
  Top Layer w10: R1.2@150,2228.62 151.38,2230 v2(175,2230)
  Signal Layer 2 w10: v2(175,2230) 315,2230 455,2370 v2(490,2370)
  Signal Layer 4 w10: v2(490,2370) 340,2370 230,2480 230,2830 J1.9@400,3000 J1.7@500,3000 J1.5@600,3000 J1.3@700,3000 J1.1@800,3000 850,3000 860,2990 860,2835 850,2825 J8.2@850,2755
VIN: C101.1 C102.1 C103.1 C104.1 C105.1 C106.1 C201.1 C202.1 C203.1 C204.1 C205.1 C206.1 C301.1 C302.1 C303.1 C304.1 C305.1 C306.1 C401.1 C402.1 C403.1 C404.1 C405.1 C406.1 C501.1 C502.1 C503.1 C504.1 C505.1 C506.1 C601.1 C602.1 C603.1 C604.1 C605.1 C606.1 C701.1 C702.1 C703.1 C704.1 C705.1 C706.1 C900.1 R41.1 R43.1 TP199.1 U100.7 U200.7 U300.7 U400.7 U500.7 U600.7 U700.7 U900.2 U900.3 | length 187.9
  Top Layer w12: R41.1@730,4363.62 730,4465 755,4490 R43.1@806.14,4490
  other v2: 1015,855 1015,880 1010,3525 1235,3525 1010,3605 1235,3605
  other v3: 880,4400 925,4400 970,4400 880,4445 925,4445 970,4445 880,4495 925,4495 970,4495 880,4540 925,4540 970,4540 880,4590 925,4590 970,4590
  other v4: 1475,795 1475,855 1475,930 1475,990 1475,1060 1475,1120 1475,1465 1475,1525 1475,1605 1475,1660 1475,1735 1475,1795 1475,2470 1475,2530 1475,2620 1475,2680 1475,2750 1475,2810 1475,3120 1475,3180 1475,3270 1475,3330 1475,3400 1475,3460 1475,3820 1475,3880 1475,3980 1475,4040 1475,4110 1475,4170 1475,4480 1475,4540 1475,4640 1475,4700 1475,4770 1475,4805 1475,5150 1475,5210 1480,5290 1480,5350 1480,5420 1480,5480
VIN_CSNIN: C2.1 C3.1 R41.2 U1.11 | length 2311.1
  Top Layer w7.87: C3.1@485,2530 548.62,2530 583.54,2495.08 U1.11@583.54,2480.87
  Top Layer w10: v3(480,2640) 480,2593.5 C2.1@476.5,2590 485,2581.5 C3.1@485,2530 ; v3(710,4270) 730,4290 R41.2@730,4316.38
  Signal Layer 2 w10: v3(480,2640) 435,2685 370,2685 335,2720 335,3035 400,3100 623.28,3100 700,3176.72 700,4260 v3(710,4270)
VIN_P: C11.1 C12.1 C13.1 J11.1 R42.1 R43.2 VIN.1 | length 185.8
  Top Layer w12: R43.2@573.86,4490 625,4490 645,4470 R42.1@645,4363.62
  other v1: 65,3845 110,3845 155,3845 200,3845 520,3845 565,3845 65,3890 110,3890 155,3890 565,3890 65,3935 110,3935 65,3980 110,3980 65,4025 110,4025 65,4070 110,4070 65,4115 110,4115 155,4115 565,4115 65,4160 110,4160 155,4160 200,4160 520,4160 565,4160
  other v3: 490,4400 535,4400 585,4400 480,4445 525,4445 480,4495 525,4495 480,4540 525,4540 536,4589 490,4590 585,4590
